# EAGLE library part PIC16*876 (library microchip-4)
MICROCONTROLLER flash type
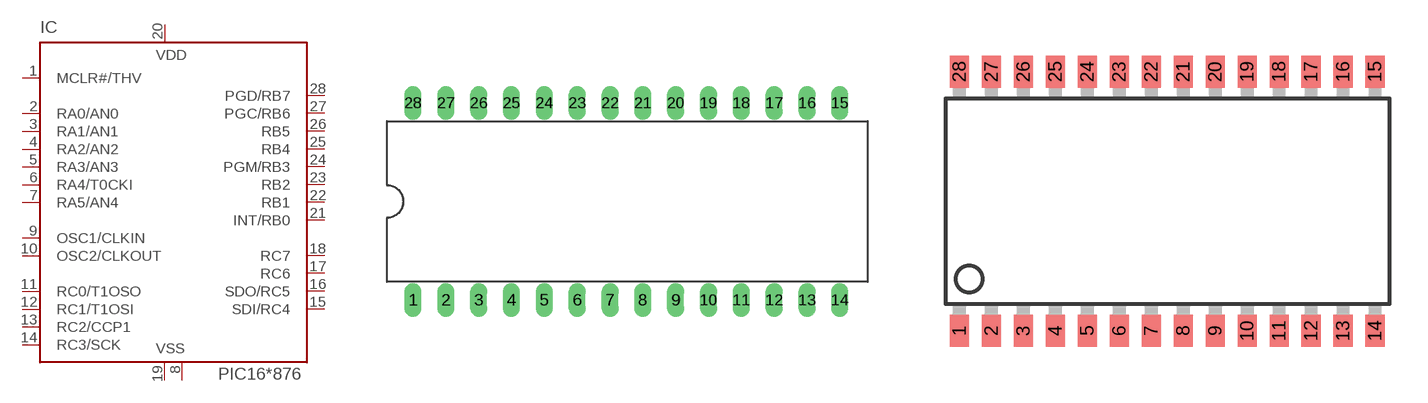
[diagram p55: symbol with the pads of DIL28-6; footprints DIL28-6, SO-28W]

Designator prefix IC

## PIC16F876P  [DIL28-6]
1  MCLR#/THV  in
2  RA0/AN0
3  RA1/AN1
4  RA2/AN2
5  RA3/AN3
6  RA4/T0CKI
7  RA5/AN4
8  VSS  pwr
9  OSC1/CLKIN  in
10  OSC2/CLKOUT  out
11  RC0/T1OSO
12  RC1/T1OSI
13  RC2/CCP1
14  RC3/SCK
15  SDI/RC4
16  SDO/RC5
17  RC6
18  RC7
19  VSS  pwr
20  VDD  pwr
21  INT/RB0
22  RB1
23  RB2
24  PGM/RB3
25  RB4
26  RB5
27  PGC/RB6
28  PGD/RB7

## PIC16F876SO  [SO-28W]
Pads as for DIL28-6

## Footprint DIL28-6 (pad centres in mm)
Dual In Line package type P
drill 0.813 long: 1 -16.51,-7.62; 2 -13.97,-7.62; 3 -11.43,-7.62; 4 -8.89,-7.62; 5 -6.35,-7.62; 6 -3.81,-7.62; 7 -1.27,-7.62; 8 1.27,-7.62; 9 3.81,-7.62; 10 6.35,-7.62; 11 8.89,-7.62; 12 11.43,-7.62; 13 13.97,-7.62; 14 16.51,-7.62; 15 16.51,7.62; 16 13.97,7.62; 17 11.43,7.62; 18 8.89,7.62; 19 6.35,7.62; 20 3.81,7.62; 21 1.27,7.62; 22 -1.27,7.62; 23 -3.81,7.62; 24 -6.35,7.62; 25 -8.89,7.62; 26 -11.43,7.62; 27 -13.97,7.62; 28 -16.51,7.62

## Footprint SO-28W (pad centres in mm)
Small Outline Wide Plastic Gull Wing 300-mil body, package type SO
smd 0.762 x 1.27: 1 -7.62,-5.207; 2 -6.35,-5.207; 3 -5.08,-5.207; 4 -3.81,-5.207; 5 -2.54,-5.207; 6 -1.27,-5.207; 7 0,-5.207; 8 1.27,-5.207; 9 2.54,-5.207; 10 3.81,-5.207; 11 5.08,-5.207; 12 6.35,-5.207; 13 7.62,-5.207; 14 8.89,-5.207; 15 8.89,5.08; 16 7.62,5.08; 17 6.35,5.08; 18 5.08,5.08; 19 3.81,5.08; 20 2.54,5.08; 21 1.27,5.08; 22 0,5.08; 23 -1.27,5.08; 24 -2.54,5.08; 25 -3.81,5.08; 26 -5.08,5.08; 27 -6.35,5.08; 28 -7.62,5.08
